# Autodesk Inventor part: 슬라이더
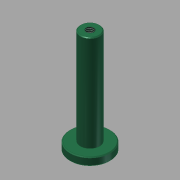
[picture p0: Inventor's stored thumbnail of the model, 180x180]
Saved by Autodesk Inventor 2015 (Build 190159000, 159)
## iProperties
Created: 2016-02
Part Number: 슬라이더
Material: 스테인리스강
Document SubType Name: Modeling
Designer: mduedu
Density: 8.08 g/cm^3
Appearance: 매끄러움 - 짙은 바다 녹색
Author: mduedu
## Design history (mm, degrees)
sketch "스케치1"
  geometry: C1 r 12.5 at (0, 0); 1 further point
  constraints: 1 centre point, 1 coincident
  dimensions: "d0" = 25 diameter of C1
extrude "돌출1" new body sketch "스케치1" distance "d1" = 5; taper "d2" = 0 deg
sketch "스케치2"
  geometry: C1 r 6 at (0, 0); 1 further point
  constraints: 1 centre point, 1 coincident
  dimensions: "d3" = 12 diameter of C1
extrude "돌출2" join sketch "스케치2" distance "d4" = 60; taper "d5" = 0 deg
chamfer "모따기1" distance "d6" = 0.5; stored, may be unused: second distance "d7" = 2, angle "d8" = 45 deg
hole "구멍1" diameter "d11" = 4.917; stored, may be unused: countersink angle "d15" = 90 deg, drill point angle "d17" = 118 deg; dims "d9" = 10, "d10" = 10, "d12" = 10, "d13" = 4, "d14" = 2, "d16" = 12
chamfer "모따기2" distance "d18" = 0.5; stored, may be unused: second distance "d19" = 2, angle "d20" = 45 deg
node "솔리드1"
